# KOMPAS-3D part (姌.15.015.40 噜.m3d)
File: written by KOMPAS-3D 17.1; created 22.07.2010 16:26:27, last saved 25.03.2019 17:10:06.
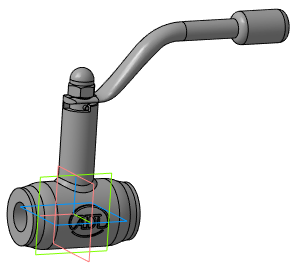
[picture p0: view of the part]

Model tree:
1. Плоскость XY
2. Плоскость ZX
3. Плоскость ZY
4. Ось X
5. Ось Y
6. Ось Z
7. Начало координат
8. Операция без истории:3  (labels: Сталь 20  ГОСТ 1050-88)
